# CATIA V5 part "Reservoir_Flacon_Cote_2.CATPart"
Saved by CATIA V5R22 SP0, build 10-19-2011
Part number: Reservoir_Flacon_Cote
Bounding box of the stored display mesh (mm): x 0 to 5, y -31 to 31, z -150 to 150
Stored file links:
  U:\S9A\PER\CAO\Assemblage\Reservoir_Flacon\Sous_Ensemble_Flacon\Reservoir_Flacon_Cote_2.CATPart
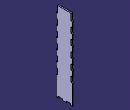
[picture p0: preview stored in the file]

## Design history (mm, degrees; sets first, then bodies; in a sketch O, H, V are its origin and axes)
Body1 (main body)
  Sketch1 on yz-plane, origin (0, 0, 0), H (0, 1, 0), V (0, 0, 1)
    line L1 (-31, 150) -> (31, 150)
    line L2 (31, 150) -> (31, -150)
    line L3 (31, -150) -> (-31, -150)
    line L4 (-31, -150) -> (-31, 150)
    length L4 = 300
    length L1 = 62
    horizontal: L1 H, L3 H
    vertical: L2 V, L4 V
    symmetry: L4 L2 V, L3 L1 H
  Pad1: profile Sketch1, direction (1, 0, 0), length 5
  Sketch2 on end face of Pad1, origin (5, 0, 0), H (0, 1, 0), V (0, 0, 1)
    point P1 (-31, 150)
    line L1 (-31, 150) -> (-26, 150)
    line L2 (-26, 150) -> (-26, 125)
    line L3 (-26, 125) -> (-31, 125)
    line L4 (-31, 125) -> (-31, 150)
    point P2 (-26, 150)
    point P3 (-26, 125)
    point P4 (-31, 125)
    reference projected point E1 (-31, 150) from vertex [face of Pad1 from Sketch1.L1 | end face of Pad1 | face of Pad1 from Sketch1.L4]
    point P5 (31, 150)
    point P6 (26, 150)
    point P7 (26, 125)
    point P8 (31, 125)
    line L5 (31, 150) -> (26, 150)
    line L6 (26, 150) -> (26, 125)
    line L7 (26, 125) -> (31, 125)
    line L8 (31, 125) -> (31, 150)
    length L4 = 25
    length L1 = 5
    horizontal: L1 H, L3 H
    vertical: L2 V, L4 V
    coincidence: P1 E1
    symmetry: P1 P5 V, P2 P6 V, P3 P7 V, P4 P8 V, L1 L5 V, L2 L6 V, L3 L7 V, L4 L8 V
  Pocket1: profile Sketch2, direction (-1, 0, 0), through (limit type 6)
  Sketch3 on end face of Pad1, origin (5, 0, 0), H (0, 1, 0), V (0, 0, 1)
    point P1 (-31, 105)
    line L1 (-31, 105) -> (-26, 105)
    line L2 (-26, 105) -> (-26, 85)
    line L3 (-26, 85) -> (-31, 85)
    line L4 (-31, 85) -> (-31, 105)
    point P2 (-26, 105)
    point P3 (-26, 85)
    point P4 (-31, 85)
    reference projected line E1 (-31, 150) -> (-31, -150) from edge [face of Pad1 from Sketch1.L4 | end face of Pad1]
    reference projected line E2 (-31, 125) -> (-26, 125) from edge [end face of Pad1 | face of Pocket1 from Sketch2.L3]
    point P5 (31, 105)
    point P6 (26, 105)
    point P7 (26, 85)
    point P8 (31, 85)
    line L5 (31, 105) -> (26, 105)
    line L6 (26, 105) -> (26, 85)
    line L7 (26, 85) -> (31, 85)
    line L8 (31, 85) -> (31, 105)
    distance L1 E2 = 20
    length L4 = 20
    length L1 = 5
    horizontal: L1 H, L3 H
    vertical: L2 V, L4 V
    coincidence: L4 E1
    symmetry: P1 P5 V, P2 P6 V, P3 P7 V, P4 P8 V, L1 L5 V, L2 L6 V, L3 L7 V, L4 L8 V
  Pocket2: profile Sketch3, direction (-1, 0, 0), through (limit type 6)
  RectPattern1: of Pocket2, direction 1 instances 5, spacing 40, along edge [face of Pad1 from Sketch1.L4 | end face of Pad1]
  Sketch4 on end face of Pad1, origin (5, 0, 0), H (0, 1, 0), V (0, 0, 1)
    point P1 (-8, -150)
    line L1 (-8, -150) -> (-23, -150)
    line L2 (-23, -150) -> (-23, -145)
    line L3 (-23, -145) -> (-8, -145)
    line L4 (-8, -145) -> (-8, -150)
    point P2 (-23, -150)
    point P3 (-23, -145)
    point P4 (-8, -145)
    reference projected line E1 (-31, -150) -> (31, -150) from edge [face of Pad1 from Sketch1.L3 | end face of Pad1]
    reference projected line E2 (-31, 150) -> (-31, -150) from edge [face of Pad1 from Sketch1.L4 | end face of Pad1]
    point P5 (8, -150)
    point P6 (23, -150)
    point P7 (23, -145)
    point P8 (8, -145)
    line L5 (8, -150) -> (23, -150)
    line L6 (23, -150) -> (23, -145)
    line L7 (23, -145) -> (8, -145)
    line L8 (8, -145) -> (8, -150)
    length L3 = 15
    length L2 = 5
    distance L2 E2 = 8
    horizontal: L1 H, L3 H
    vertical: L2 V, L4 V
    coincidence: L1 E1
    symmetry: P1 P5 V, P2 P6 V, P3 P7 V, P4 P8 V, L1 L5 V, L2 L6 V, L3 L7 V, L4 L8 V
  Pocket3: profile Sketch4, direction (-1, 0, 0), through (limit type 3)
